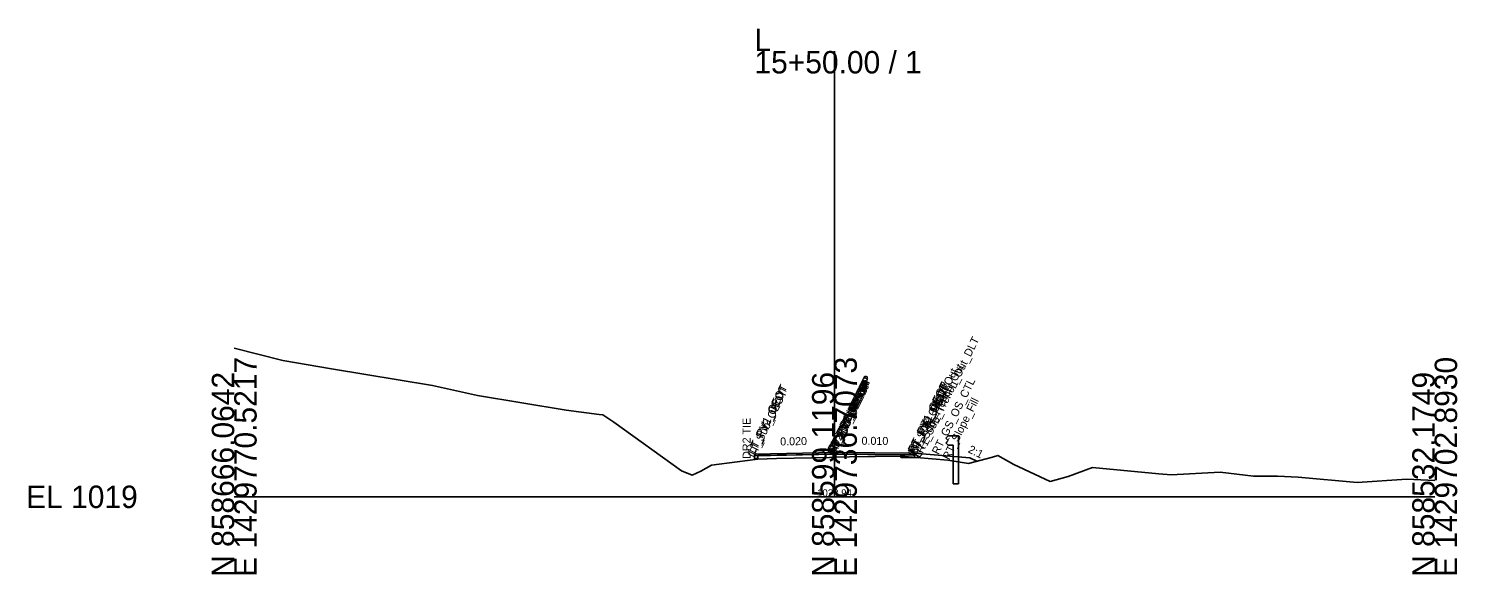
# Model space of a CAD drawing. Extents: x -26 to 153, y -10 to 13058.
# Drawn here: x -25.7 to 152.8, y 7990.3 to 8058.5 of the extents above; entities that cross this region are included whole.
import ezdxf

# ---------------------------------------------------------------- set-up
doc = ezdxf.new("R2010")
doc.units = 0
for name, color, linetype in [('Default', 7, 'Continuous'), ('Exist Cross Section Cell', 7, 'Continuous'), ('Exist XS Ground Line', 7, 'Continuous'), ('Prop CMT Guardrail Graphics', 7, 'Continuous'), ('Prop CMT Pvmt Course 1', 7, 'Continuous'), ('Prop CMT Pvmt Course 2', 7, 'Continuous'), ('Prop CMT Pvmt Course 2 Wedge', 7, 'Continuous'), ('Prop CMT Pvmt Surface', 7, 'Continuous'), ('Prop CMT Pvmt Surface Shoulder', 7, 'Continuous'), ('Prop CMT Pvmt Wedge Surface 2', 7, 'Continuous'), ('Prop CMT Shld Paved Course 1', 7, 'Continuous'), ('Prop CMT Shld Paved Course 2', 7, 'Continuous'), ('Prop CMT Slope Grass', 7, 'Continuous'), ('Prop CMT Subgrade Daylight Point', 7, 'Continuous'), ('Prop CMT Subgrade Earthwork', 7, 'Continuous'), ('Prop CMT Template Flag', 7, 'Continuous'), ('Prop XS Dump Level', 7, 'Continuous'), ('Prop XS SE Text', 7, 'Continuous'), ('Prop XS Side Slope Text', 7, 'Continuous'), ('Prop XSC Text', 7, 'Continuous')]:
    doc.layers.add(name, color=color, linetype=linetype)

msp = doc.modelspace()

# ---------------------------------------------------------------- linework, layer by layer
at = {"layer": 'Exist Cross Section Cell'}
for p, q in [((75, 8000), (75, 8055.69)), ((0, 8000), (75, 8000)), ((75, 8000), (150, 8000))]:
    msp.add_line(p, q, dxfattribs=at)
at = {"layer": 'Exist XS Ground Line'}
msp.add_lwpolyline([(0, 8018.56), (6.09, 8017.04), (12.14, 8015.99), (24.78, 8013.9), (30.42, 8012.64), (41.48, 8010.84), (45.59, 8010.28), (46.05, 8010.25), (47.45, 8009.32), (55.89, 8003.24), (57.23, 8002.69), (58.31, 8003.21), (59.63, 8003.97), (62.85, 8004.39), (65.44, 8004.71), (67.74, 8004.79), (74.37, 8004.92), (75, 8004.94), (76.86, 8004.99), (83.31, 8005.08), (89.18, 8004.56), (91.75, 8004.15), (94.74, 8004.97), (95.43, 8005.17), (97.42, 8004.03), (101.94, 8001.92), (104.21, 8002.52), (107.25, 8003.67), (115.54, 8002.88), (117.09, 8002.76), (123.2, 8003.08), (127.37, 8002.6), (130.36, 8002.57), (132.94, 8002.47), (140.33, 8001.79), (146.53, 8002.19), (150, 8002.05)], dxfattribs=at)
at = {"layer": 'Prop CMT Guardrail Graphics'}
for points in [[(90.52, 8007.63), (89.19, 8007.63), (88.92, 8007.34)], [(88.92, 8007.34), (89.19, 8007.05)], [(90.52, 8001.63), (90.52, 8007.63)], [(89.19, 8007.05), (88.92, 8006.76)], [(88.92, 8006.76), (89.19, 8006.46), (89.85, 8006.46)], [(89.85, 8006.46), (89.85, 8001.63)], [(89.85, 8001.63), (90.52, 8001.63)]]:
    msp.add_lwpolyline(points, dxfattribs=at)
at = {"layer": 'Prop CMT Pvmt Course 1'}
for points in [[(75, 8005.54), (65, 8005.34)], [(75, 8005.34), (75, 8005.54)], [(75, 8005.54), (85, 8005.44)], [(75, 8005.34), (75, 8005.54)], [(85, 8005.44), (85, 8005.24)], [(65, 8005.34), (65, 8005.14)], [(65, 8005.14), (65.44, 8005.15)], [(75, 8005.34), (65.44, 8005.15)], [(75, 8005.34), (83.31, 8005.25)], [(85, 8005.24), (83.31, 8005.25)]]:
    msp.add_lwpolyline(points, dxfattribs=at)
msp.add_lwpolyline([(75, 8005.34), (75, 8005.42), (75, 8005.42), (75, 8005.34)], close=True, dxfattribs=at)
msp.add_lwpolyline([(75, 8005.34), (75, 8005.42), (75, 8005.42), (75, 8005.34)], close=True, dxfattribs=at)
at = {"layer": 'Prop CMT Pvmt Course 2'}
for points in [[(65, 8005.14), (65, 8004.8)], [(65, 8004.8), (65.44, 8004.81)], [(65.44, 8004.81), (65.44, 8005.15)], [(83.31, 8004.92), (83.31, 8005.25)], [(85, 8004.9), (83.31, 8004.92)], [(85, 8005.24), (85, 8004.9)]]:
    msp.add_lwpolyline(points, dxfattribs=at)
at = {"layer": 'Prop CMT Pvmt Course 2 Wedge'}
msp.add_lwpolyline([(65.44, 8005.15), (65.44, 8004.71)], dxfattribs=at)
at = {"layer": 'Prop CMT Pvmt Surface'}
for points in [[(75, 8005.54), (65, 8005.34)], [(75, 8005.54), (85, 8005.44)]]:
    msp.add_lwpolyline(points, dxfattribs=at)
at = {"layer": 'Prop CMT Pvmt Surface Shoulder'}
msp.add_lwpolyline([(85, 8005.44), (85, 8005.44)], dxfattribs=at)
at = {"layer": 'Prop CMT Pvmt Wedge Surface 2'}
for points in [[(75, 8005.34), (65, 8005.14)], [(75, 8005.34), (85, 8005.24)]]:
    msp.add_lwpolyline(points, dxfattribs=at)
at = {"layer": 'Prop CMT Shld Paved Course 1'}
for points in [[(85, 8005.44), (85, 8005.44)], [(85, 8005.44), (85.21, 8005.23)], [(85, 8005.24), (85, 8005.44)], [(85.21, 8005.23), (85, 8005.24)]]:
    msp.add_lwpolyline(points, dxfattribs=at)
at = {"layer": 'Prop CMT Shld Paved Course 2'}
for points in [[(85, 8005.24), (85.21, 8005.23)], [(85, 8004.9), (85, 8005.24)], [(85.55, 8004.89), (85, 8004.9)], [(85.21, 8005.23), (85.21, 8005.23)], [(85.21, 8005.23), (85.55, 8004.89)]]:
    msp.add_lwpolyline(points, dxfattribs=at)
at = {"layer": 'Prop CMT Slope Grass'}
for points in [[(85, 8005.44), (88.92, 8005.13)], [(88.92, 8005.13), (91.92, 8004.89)], [(91.92, 8004.89), (92.81, 8004.44)]]:
    msp.add_lwpolyline(points, dxfattribs=at)
at = {"layer": 'Prop CMT Subgrade Earthwork'}
for p, q in [((65.44, 8005.15), (65.44, 8004.71)), ((83.31, 8005.08), (83.31, 8004.92))]:
    msp.add_line(p, q, dxfattribs=at)
for points in [[(65.44, 8004.81), (65, 8004.8)], [(83.31, 8004.92), (85, 8004.9)], [(85, 8004.9), (85.55, 8004.89)], [(85.55, 8004.89), (86.02, 8005.36)]]:
    msp.add_lwpolyline(points, dxfattribs=at)
at = {"layer": 'Prop CMT Template Flag'}
msp.add_line((65, 8005.34), (65, 8004.66), dxfattribs=at)

# ---------------------------------------------------------------- texts
at = {"layer": 'Default'}
msp.add_text('-', height=0.0001, dxfattribs=at).set_placement((0, 8000))
at = {"layer": 'Exist Cross Section Cell'}
for s, p in [('L', (65, 8055.69)), ('15+50.00 / 1', (65, 8052.89)), ('EL 1019', (-26, 7998.6))]:
    msp.add_text(s, height=2.8, dxfattribs=at).set_placement(p)
for s, p in [('E 1429770.5217', (2.8, 7990)), ('E 1429736.7073', (77.8, 7990)), ('E 1429702.8930', (152.8, 7990)), ('N 858666.0642', (0, 7990)), ('N 858599.1196', (75, 7990)), ('N 858532.1749', (150, 7990))]:
    msp.add_text(s, height=2.8, rotation=90, dxfattribs=at).set_placement(p)
at = {"layer": 'Prop CMT Subgrade Daylight Point'}
msp.add_text('1023.94', height=0.9, dxfattribs=at).set_placement((72.83, 8000.04))
at = {"layer": 'Prop XS Dump Level'}
for s, p in [('RT_Sub_Trench_Out_DLT', (86.02, 8005.36)), ('RT_Sub_Trench_Out', (85.55, 8004.89)), ('RT_PV1_OEEOP', (75, 8005.42)), ('RT_PV2_OEEOP', (75, 8005.34)), ('LT_PV1_OEEOP', (75, 8005.42)), ('LT_PV2_OEEOP', (75, 8005.34)), ('RT_Sub_OEEOP', (75, 8005)), ('RT_PV1_IEEOP', (75, 8005.42)), ('RT_PV2_IEEOP', (75, 8005.34)), ('LT_Sub_OEEOP', (75, 8005)), ('LT_PV1_IEEOP', (75, 8005.42)), ('RT_PV1_OEOT', (85, 8005.44)), ('RT_PS1_OEOP', (85, 8005.44)), ('RT_PS2_Shelf_Out', (85.21, 8005.23)), ('RT_GS_OS_CTL', (88, 8005.2)), ('LT_PV1_OEOT', (65, 8005.34)), ('LT_PV2_OEOT', (65, 8005.14)), ('LT_Sub_OEOT', (65, 8004.8)), ('LT_PV2_IEEOP', (75, 8005.34)), ('RT_PV2_OEOT', (85, 8005.24)), ('RT_Sub_OEOT', (85, 8004.9)), ('RT_PS2_OEOP', (85.21, 8005.23)), ('PV1_PGL', (75, 8005.54)), ('RT_Slope_Fill', (89.34, 8004.53)), ('PV2_PGL', (75, 8005.34))]:
    msp.add_text(s, height=1, rotation=63.5833, dxfattribs=at).set_placement(p)
at = {"layer": 'Prop XS SE Text'}
for s, rotation, p in [('0.020', 1.1458, (68.23, 8006.41)), ('0.010', 359.4271, (78.38, 8006.51))]:
    msp.add_text(s, height=1, rotation=rotation, dxfattribs=at).set_placement(p)
at = {"layer": 'Prop XS Side Slope Text'}
msp.add_text('2:1', height=1, rotation=333.4349, dxfattribs=at).set_placement((91.62, 8005.6))
at = {"layer": 'Prop XSC Text'}
msp.add_text('DR2 TIE', height=1, rotation=90, dxfattribs=at).set_placement((64.52, 8004.74))

doc.saveas('drawing.dxf')
